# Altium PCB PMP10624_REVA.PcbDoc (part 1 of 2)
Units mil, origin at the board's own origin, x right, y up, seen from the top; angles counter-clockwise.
Board outline 2850 x 2600 mil, 4 copper layers (Top Layer, Signal Layer 1, Signal Layer 2, Bottom Layer), stack 61.2 mil thick; 108 components, 51 nets, 253 pads, 67 vias.
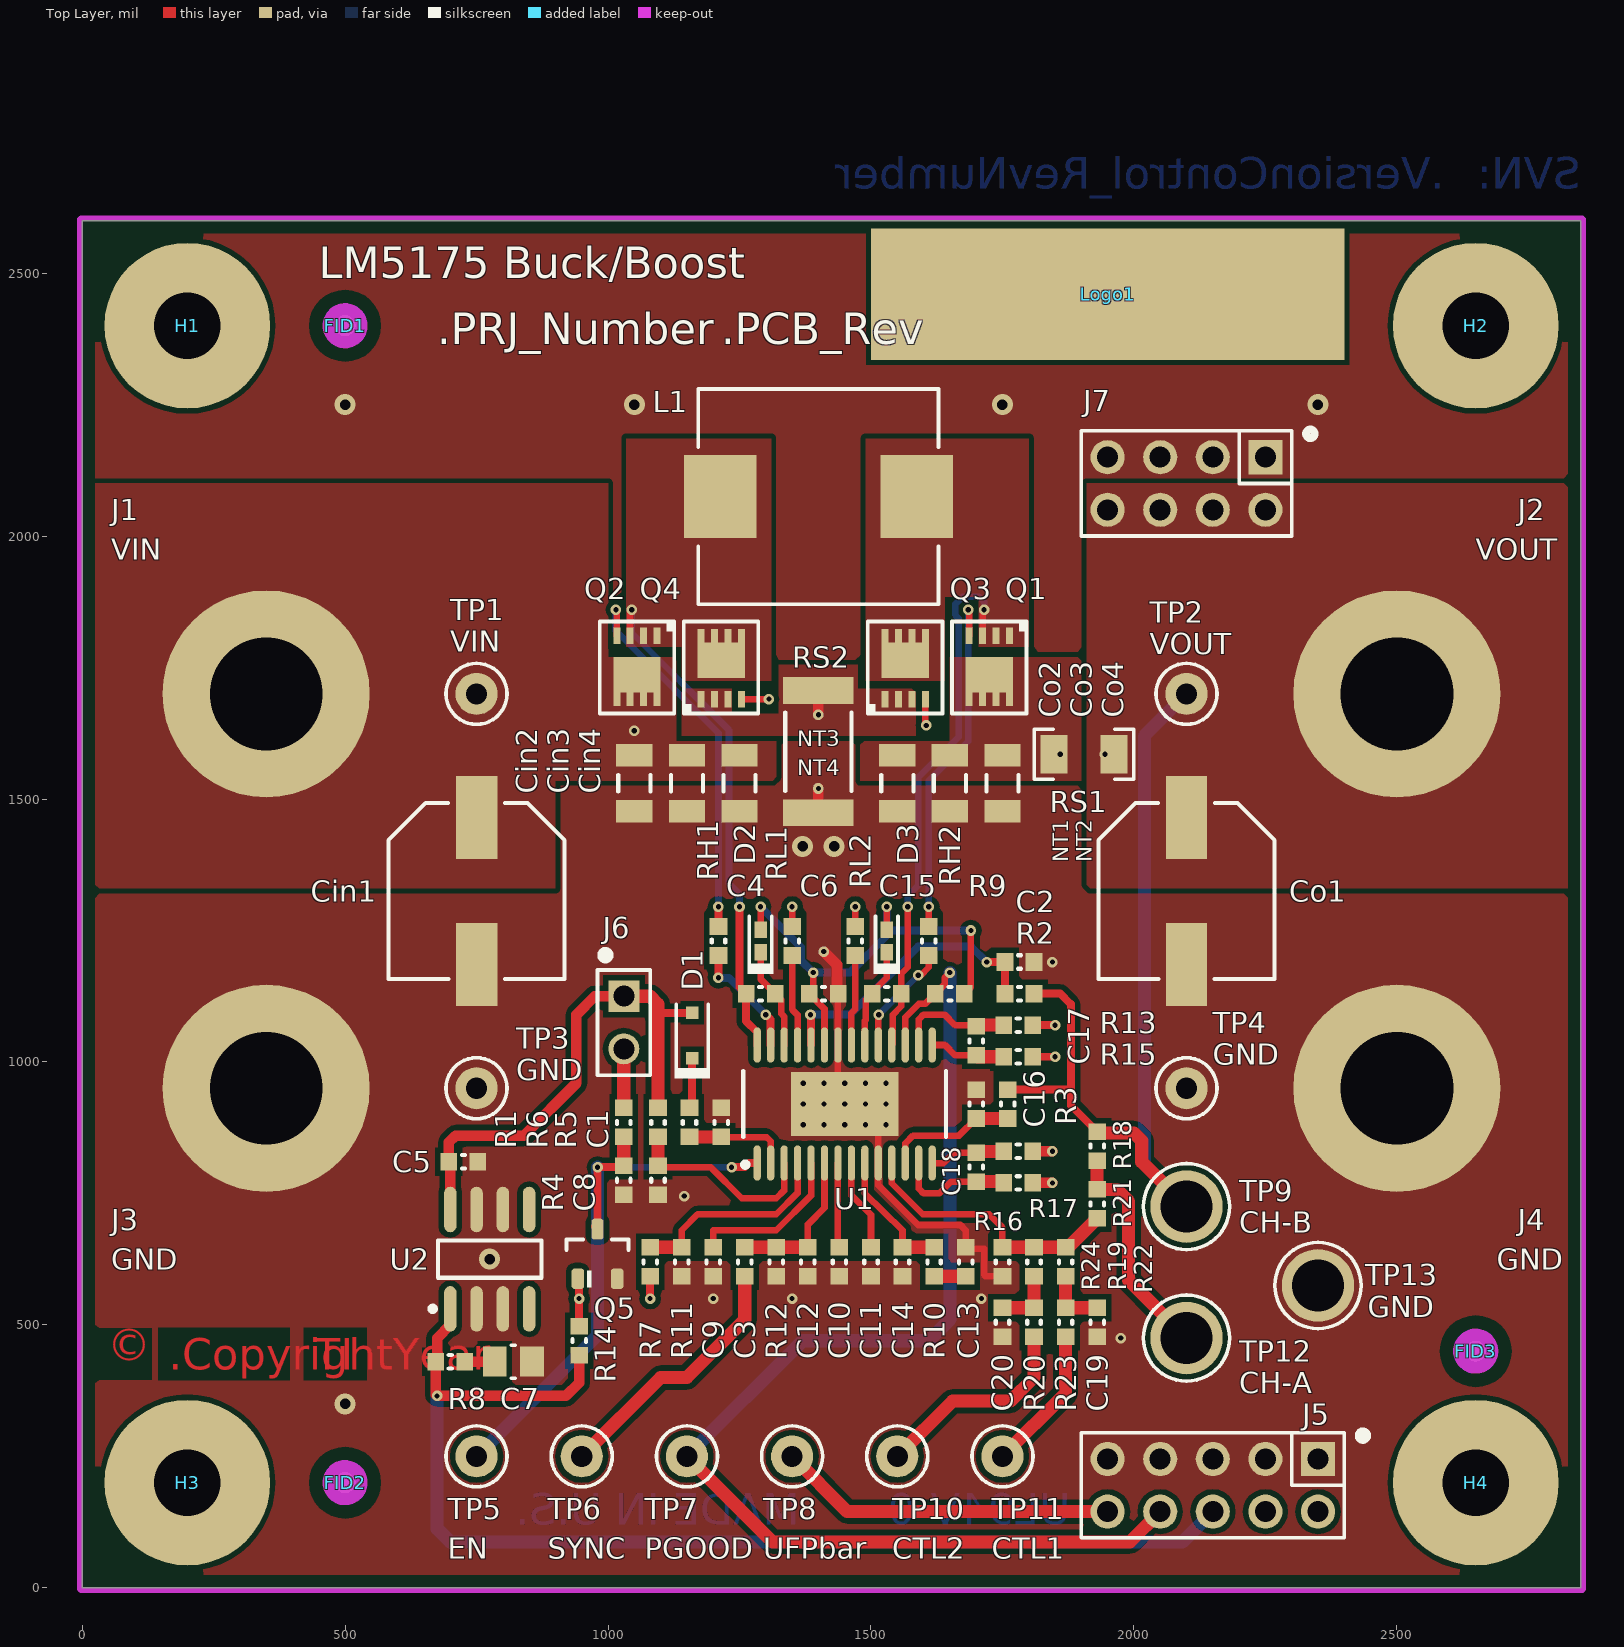
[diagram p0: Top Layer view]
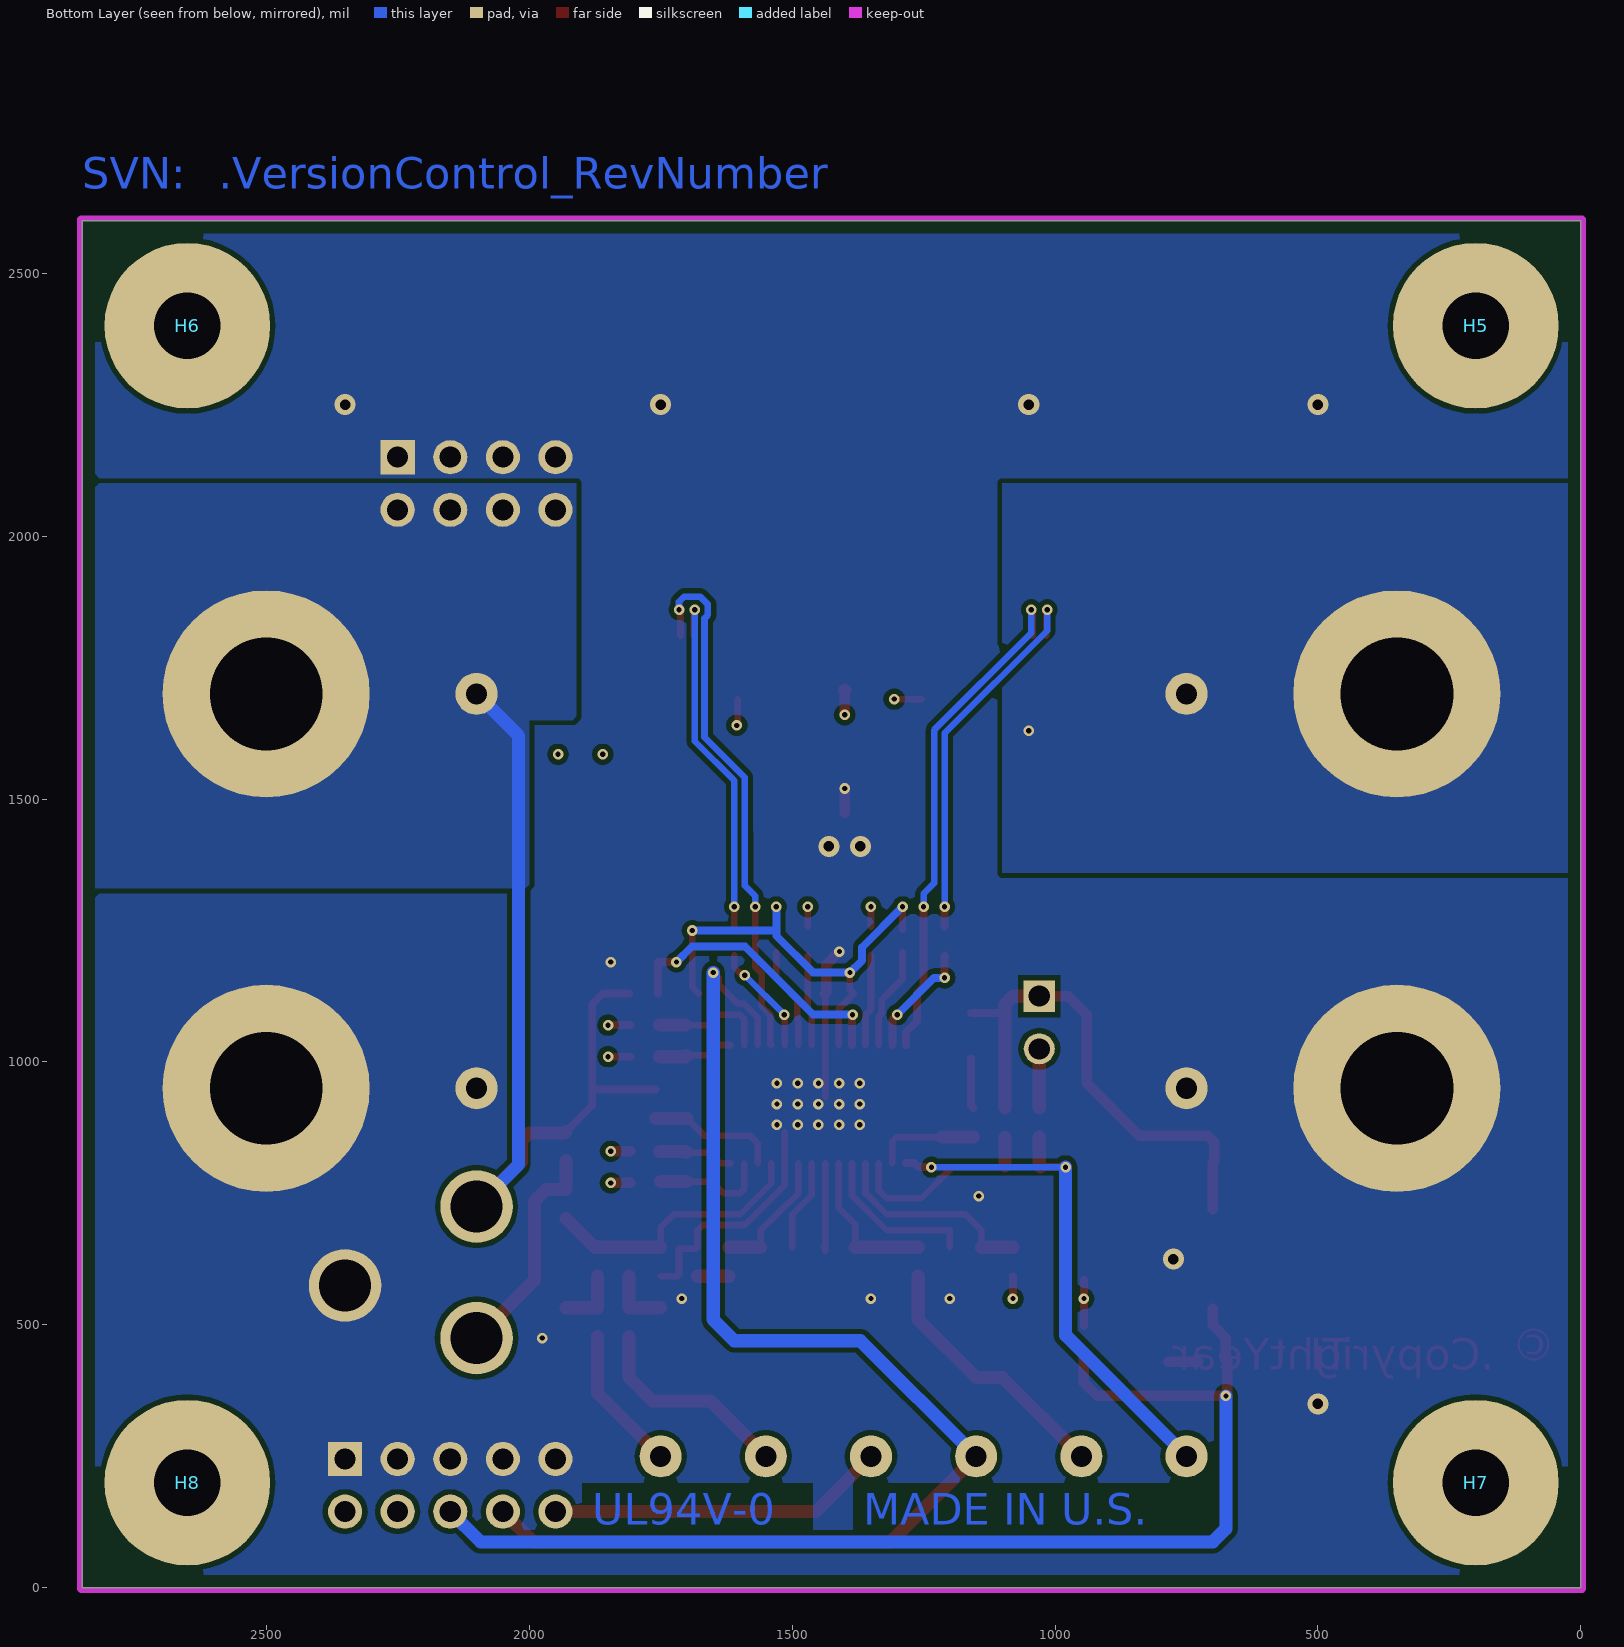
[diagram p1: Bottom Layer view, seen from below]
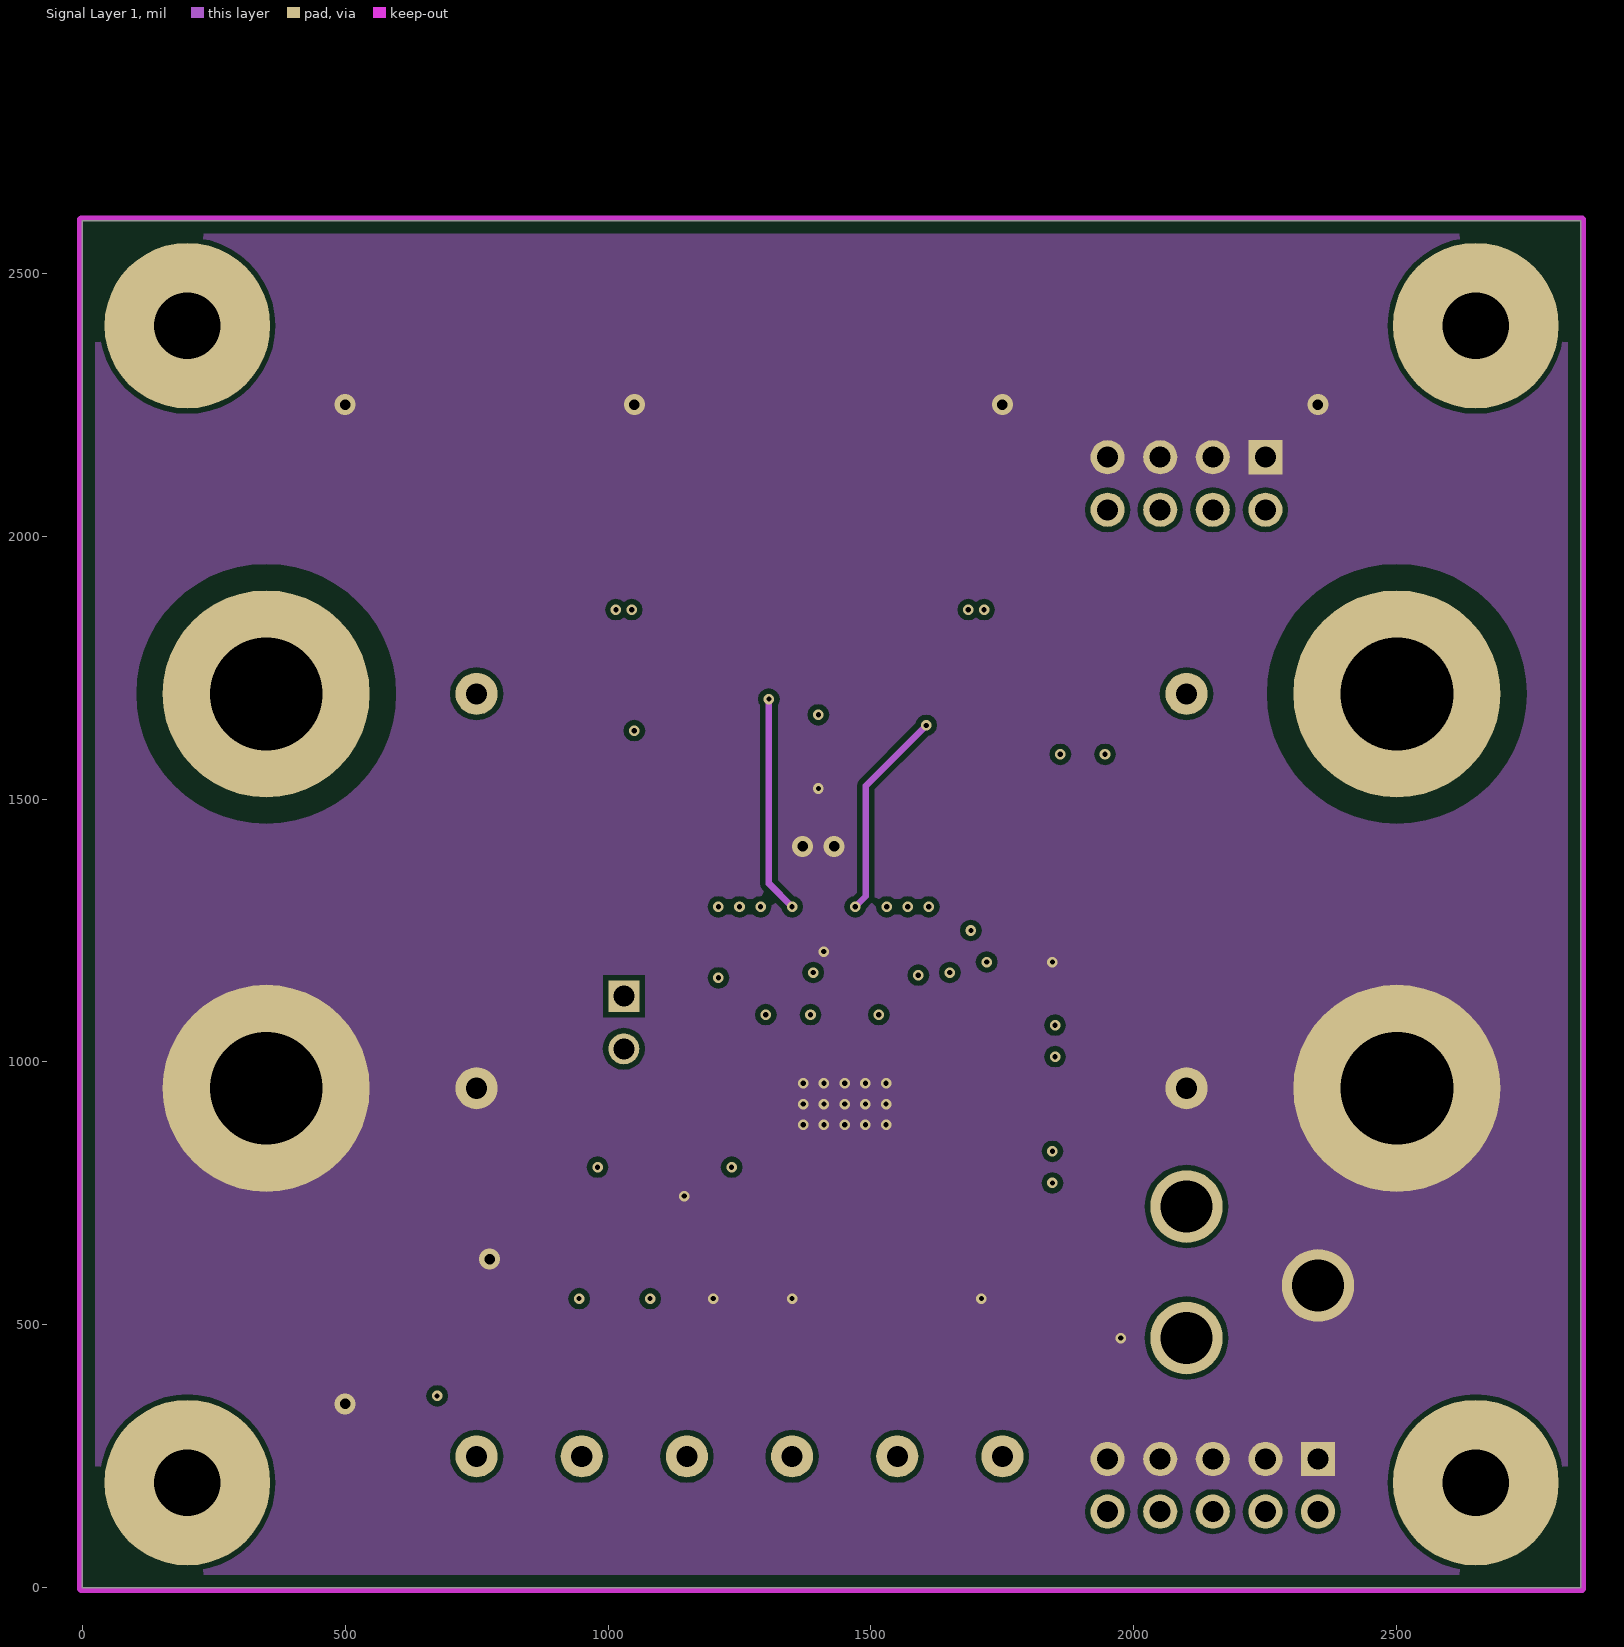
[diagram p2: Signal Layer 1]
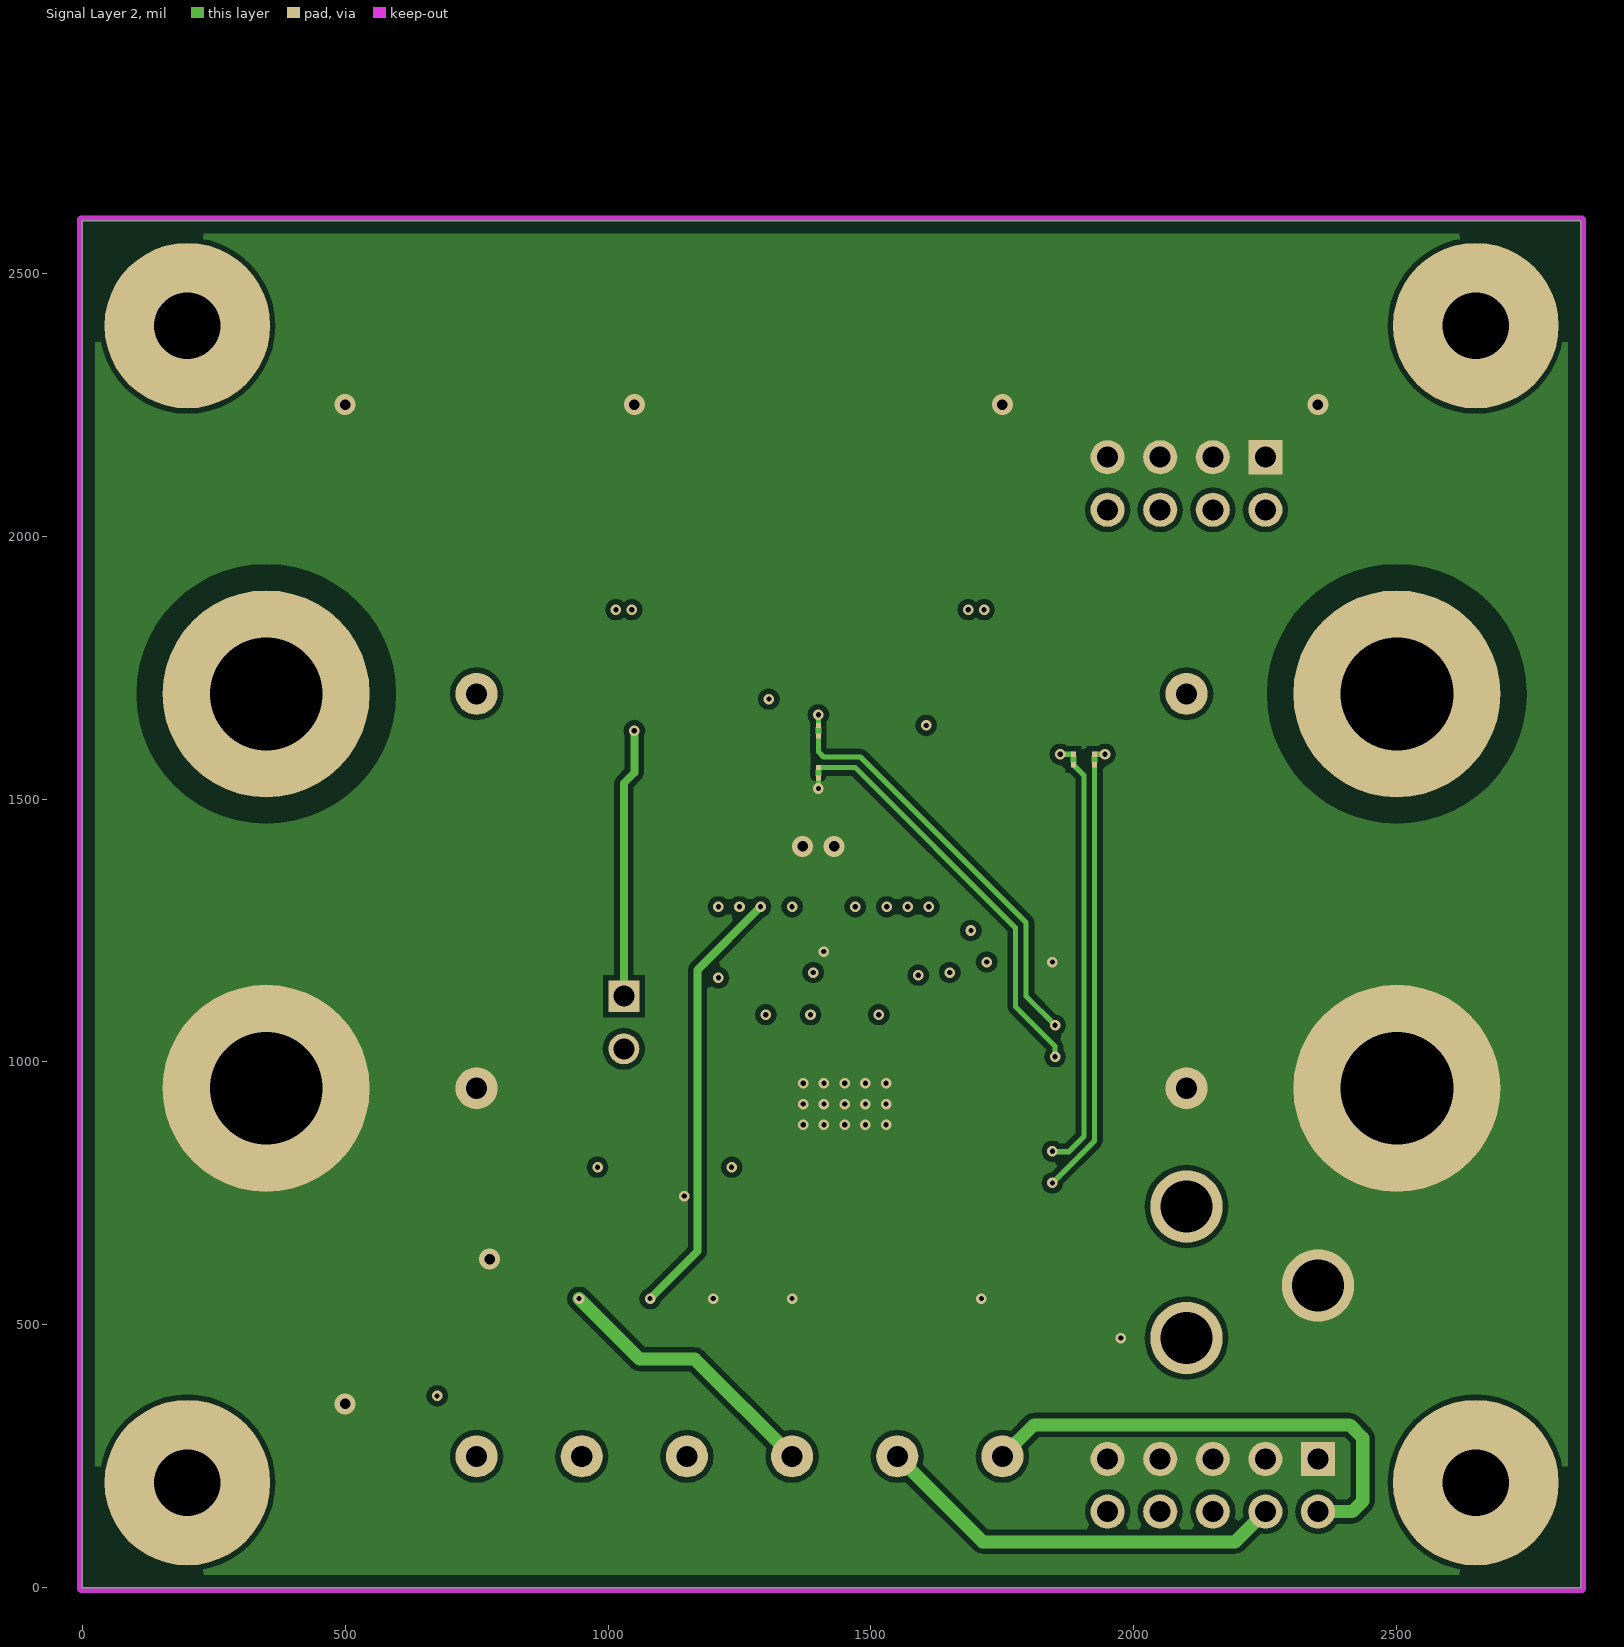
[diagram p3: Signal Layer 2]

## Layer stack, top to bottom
Top Solder: solder mask 0.4, Solder Resist, Dk 3.5
Top Layer: signal copper 2.8
Dielectric1: core 20, FR-4, Dk 4.8
Signal Layer 1: signal copper 1.4
Dielectric 2: prepreg 12.8, Dk 4.2
Signal Layer 2: signal copper 1.4
Dielectric 3: core 20, FR-4, Dk 4.8
Bottom Layer: signal copper 2.8
Bottom Solder: solder mask 0.4, Solder Resist, Dk 3.5

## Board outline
0,0 2850,0 2850,2600 0,2600

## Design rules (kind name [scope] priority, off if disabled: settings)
AcuteAngle [All] p1: minimum=4.50000000000000E+0001 checktracksonly=FALSE
AssemblyTestPointUsage [All] p1: valid=2
Clearance Clearance_IHLW [HasFootprint('IHLW-4040CF') vs IsKeepOut] p1: gap=10
Clearance Clearance_Keepouts [((IsTrack Or IsArc) And Not InPoly) And IsFree and IsKeepOut vs ((IsTrack Or IsArc) And Not InPoly) And IsFree and IsKeepOut] p2: gap=0
Clearance Clearance_BoardEdge_MountingHoles [OnCopper and InComponentClass('Mounting Holes') vs IsKeepOut] p3: gap=40
Clearance Clearance_BoardEdge_Poly [OnCopper and InPoly vs IsKeepOut] p4: gap=25
Clearance Clearance_BoardEdge [OnCopper and Not InComponentClass('Logo') and not InComponentClass('FiducialMark') and not InRegion(1000,500,4000,800) and Not IsKeepout vs IsKeepOut] p5: gap=75
Clearance Clearance_Poly [InPolygon] p6: gap=10
Clearance [All] p7: gap=5.91
ComponentClearance ComponentClearance_Shunt [InComponentClass('Header') vs InComponentClass('Shunt')] p1: gap=0 collisioncheckmode=3 verticalgap=0 showdistances=FALSE
ComponentClearance ComponentClearance_MountingHoles_FiducialMarks [InComponentClass('Mounting Holes') vs InComponentClass('FiducialMark')] p2: gap=50 collisioncheckmode=3 verticalgap=10 showdistances=FALSE
ComponentClearance ComponentClearance_Logo [InComponentClass('Logo')] p3: gap=50 collisioncheckmode=3 verticalgap=10 showdistances=FALSE
ComponentClearance ComponentClearance_ScrewToNut [(HasFootprint('NY PMS 440 0025 PH')) vs (HasFootprint('Keystone_1902C'))] p4: gap=5 collisioncheckmode=3 verticalgap=10 showdistances=FALSE
ComponentClearance ComponentClearance_MountingHoles [InComponentClass('Mounting Holes')] p5: gap=120 collisioncheckmode=3 verticalgap=100000 showdistances=FALSE
ComponentClearance ComponentClearance_SMTtoSMT [IsSMTComponent vs IsSMTComponent] p6: gap=20 collisioncheckmode=3 verticalgap=20 showdistances=FALSE
ComponentClearance ComponentClearance_SmallPassives [HasFootprint('0201*') or HasFootprint('0402*') or HasFootprint('0508') or HasFootprint('0603*') or HasFootprint('0612') or HasFootprint('0805*') or HasFootprint('0815*') or HasFootprint('0830*') or HasFootprint('1206*') or HasFootprint('1210*') or HasFootprint('1808*') or HasFootprint('1812*') or HasFootprint('1825*') or HasFootprint('2010*') or HasFootprint('2220*') or HasFootprint('2225*') or HasFootprint('2512*') or HasFootprint('2728*') or HasFootprint('3518*') or HasFootprint('Net-Tie_10mil') vs HasFootprint('0201*') or HasFootprint('0402*') or HasFootprint('0508') or HasFootprint('0603*') or HasFootprint('0612') or HasFootprint('0805*') or HasFootprint('0815*') or HasFootprint('0830*') or HasFootprint('1206*') or HasFootprint('1210*') or HasFootprint('1808*') or HasFootprint('1812*') or HasFootprint('1825*') or HasFootprint('2010*') or HasFootprint('2220*') or HasFootprint('2225*') or HasFootprint('2512*') or HasFootprint('2728*') or HasFootprint('3518*') or HasFootprint('Net-Tie_10mil')] p7: gap=20 collisioncheckmode=3 verticalgap=10 showdistances=FALSE
ComponentClearance ComponentClearance_THtoSMT [IsThruComponent vs IsSMTComponent] p8: gap=50 collisioncheckmode=3 verticalgap=30 showdistances=FALSE
ComponentClearance ComponentClearance_THtoTH [IsThruComponent vs IsThruComponent] p9: gap=100 collisioncheckmode=3 verticalgap=30 showdistances=FALSE
ComponentClearance [All] p10: gap=40 collisioncheckmode=3 verticalgap=10 showdistances=FALSE
DiffPairsRouting [All] p1: maxlimit=100 minlimit=10 mostfreqgap=10 toplayer_minwidth=7.5 toplayer_maxwidth=20 toplayer_prefwidth=15 midlayer1_minwidth=7.5 midlayer1_maxwidth=20 midlayer1_prefwidth=15 midlayer2_minwidth=7.5 midlayer2_maxwidth=20 midlayer2_prefwidth=15 bottomlayer_minwidth=7.5 bottomlayer_maxwidth=20 bottomlayer_prefwidth=15 maxuncoupledlength=1000
FabricationTestPointUsage TestPointUsage [All] p1: valid=2 allowmultiple=FALSE
FabricationTestpoint Testpoint [All] p1: side=3 testpointundercomponent=TRUE minsize=40 maxsize=100 preferedsize=60 minholesize=0 maxholesize=40 preferedholesize=32 testpointgrid=1 allowsidetop=TRUE allowsidebottom=TRUE usegrid=TRUE gridtolerance=0.01
FanoutControl Fanout_LCC [IsLCC] p1: bgadir=Out bgaviamode=Centered fanoutstyle=Auto fanoutdirection=Alternating viagrid=1 // Fanout_LCC (Default Rule)
FanoutControl Fanout_BGA [IsBGA] p2: bgadir=Out bgaviamode=Centered fanoutstyle=Auto fanoutdirection=Alternating viagrid=1 // Fanout_BGA (Default Rule)
FanoutControl Fanout_Default [All] p4: bgadir=Out bgaviamode=Centered fanoutstyle=Auto fanoutdirection=Alternating viagrid=1 // Fanout_Default (Default Rule)
FanoutControl Fanout_Small [(CompPinCount < 5)] p5: bgadir=Out bgaviamode=Centered fanoutstyle=Auto fanoutdirection=OutThenIn viagrid=1 // Fanout_Small (Default Rule)
HoleSize [All] p1: absolutevalues=TRUE maxlimit=271 minlimit=8 maxpercent=80.000 minpercent=20.000
MinimumAnnularRing MinimumAnnularRing_ThermalPadVias [IsVia and InAnyComponent] p1: minimumring=5
MinimumAnnularRing [All] p2: minimumring=5
MinimumSolderMaskSliver MinimumSolderMaskSliver_Logo [InComponentClass('Logo') vs InComponentClass('Logo')] p1: minsoldermaskwidth=0.7
MinimumSolderMaskSliver [All] p2: minsoldermaskwidth=2.95
PlaneConnect [All] p1: planeconnectstyle=Direct reliefexpansion=10 reliefentries=4 reliefconductorwidth=10 reliefairgap=10
PolygonConnect [All] p1: connectstyle=Direct reliefconductorwidth=10 reliefentries=4 polygonreliefangle="90 Angle" airgapwidth=10
RoutingVias ThermalPadVias [IsVia and InAnyComponent] p1: holewidth=7.87 width=19.68 viastyle="Through Hole" minholewidth=7.87 minwidth=19.68 maxholewidth=12.99 maxwidth=23.62
RoutingVias [All] p2: holewidth=16 width=34 viastyle="Through Hole" minholewidth=7.87 minwidth=20 maxholewidth=40 maxwidth=65
SilkToBoardRegionClearance [Not ((IsComment or IsDesignator) And (Hide <> 'False')) and not InRegion(1000,500,4000,800)] p1:
SilkToSilkClearance SilkToSilkClearance_Pb-FreeLogo [(HasFootprint('Pb-Free_Overlay_Medium') OR HasFootprint('Pb-Free_Overlay_Small')) vs (HasFootprint('Pb-Free_Overlay_Medium') OR HasFootprint('Pb-Free_Overlay_Small'))] p1: silktosilkclearance=0
SilkToSilkClearance [All] p2: silktosilkclearance=5
SilkToSolderMaskClearance "Silk to Solder Mask Opening" [All] p1: minsilkscreentomaskgap=1 clearancetoexposedcopper=FALSE
SolderMaskExpansion [All] p1: expansion=1.97
UnpouredPolygon [All] p1: allowunpoured=FALSE
Width [All] p1: maxlimit=100 minlimit=6 preferedwidth=10 checkconnectedcopper=TRUE
14 further rules are at their usual default settings.

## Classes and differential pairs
component class "Mounting Holes": H1 H2 H3 H4
component class Logo: Logo1
component class PMP10624_REVA_Sh2: FID1 FID2 FID3 H1 H2 H3 H4 H5 H6 H7 H8 Logo1 ZZ1 ZZ2 ZZ3
component class FiducialMark: FID1 FID2 FID3
component class AssemblyNote: ZZ1 ZZ2 ZZ3
component class Header: J5 J6 J7
differential pair ISNS_OUT: +ISNS_OUT_P -ISNS_OUT_N
differential pair HDRV2: +HDRV2_P -HDRV2_N
differential pair HDRV1: +HDRV1_P -HDRV1_N
differential pair CS: +CS_P -CS_N

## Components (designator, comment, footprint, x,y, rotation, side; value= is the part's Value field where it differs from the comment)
C1 "C1608X7R1H224K080AB" 0603L 1215,885 r90 top
C2 "C1608X7R1H224K080AB" 0603L 1782.44,1190 r0 top
C3 "GRM1885C1H101JA01D" 0603L 1260,620 r90 top
C4 "06033C104JAT2A" 0603L 1290,1130 r180 top
C5 "C1608X7R1H224K080AB" 0603L 725,810 r0 top
C6 "GRM188R71C105KA12D" 0603L 1410,1130 r0 top
C7 "EMK212BB7106MG-T" 0805_145 820,430 r0 top
C8 "C1608X7R1H224K080AB" 0603L 1095,775 r90 top
C9 "CRCW06030000Z0EA" 0603L 1200,620 r90 top
C10 "GRM1885C1H101JA01D" 0603L 1440,620 r270 top
C11 "GRM188R71H473KA61D" 0603L 1500,620 r270 top
C12 "DNP" 0603L 1380,620 r90 top
C13 "GRM188R71H223KA01D" 0603L 1680,620 r90 top
C14 "GRM1885C1H101JA01D" 0603L 1560,620 r270 top
C15 "06033C104JAT2A" 0603L 1530,1130 r180 top
C16 "C1608X7R1H224K080AB" 0603L 1700,920 r90 top
C17 "DNP" 0603L 1700,1040 r270 top
C18 "DNP" 0603L 1700,800 r90 top
C19 "06033C104JAT2A" 0603L 1930,505 r270 top
C20 "06033C104JAT2A" 0603L 1750,505 r270 top
Cin1 "EEE-FK1J680UP" SM_RADIAL_F 750,1325 r270 top
Cin2 "GRM31CR71H475KA12L" 1206L 1050,1530 r270 top
Cin3 "GRM31CR71H475KA12L" 1206L 1150,1530 r270 top
Cin4 "GRM31CR71H475KA12L" 1206L 1250,1530 r270 top
Co1 "EEE-FK1J680UP" SM_RADIAL_F 2100,1325 r270 top
Co2 "GRM31CR71H475KA12L" 1206L 1550,1530 r270 top
Co3 "GRM31CR71H475KA12L" 1206L 1650,1530 r270 top
Co4 "GRM31CR71H475KA12L" 1206L 1750,1530 r270 top
D1 "BAT54HT1G" sod-323 1160,1050 r90 top
D2 "BAS516,115" SOD-523 1290,1230 r90 top
D3 "BAS516,115" SOD-523 1530,1230 r90 top
FID1 "Fiducial" Fiducial10-20 500,2400 r0 top
FID2 "Fiducial" Fiducial10-20 500,200 r0 top
FID3 "Fiducial" Fiducial10-20 2650,450 r0 top
H1 "NY PMS 440 0025 PH" "NY PMS 440 0025 PH" 200,2400 r0 top locked
H2 "NY PMS 440 0025 PH" "NY PMS 440 0025 PH" 2650,2400 r0 top locked
H3 "NY PMS 440 0025 PH" "NY PMS 440 0025 PH" 200,200 r0 top locked
H4 "NY PMS 440 0025 PH" "NY PMS 440 0025 PH" 2650,200 r0 top locked
H5 "1902C" Keystone_1902C 200,2400 r180 bottom locked
H6 "1902C" Keystone_1902C 2650,2400 r180 bottom locked
H7 "1902C" Keystone_1902C 200,200 r180 bottom locked
H8 "1902C" Keystone_1902C 2650,200 r180 bottom locked
J1 "VIN" Keystone_575-4 350,1700 r0 top
J2 "VOUT" Keystone_575-4 2500,1700 r0 top
J3 "GND" Keystone_575-4 350,950 r0 top
J4 "GND" Keystone_575-4 2500,950 r0 top
J5 "PEC05DAAN" CONN_PEC05DAAN 2150,195 r180 top
J6 "PEC02SAAN" CONN_PEC02SAAN 1030,1075 r270 top
J7 "PEC04DAAN" CONN_PEC04DAAN 2100,2100 r180 top
L1 "IHLP4040DZER6R8M01" IHLP-4040DZ 1400,2075 r0 top
Logo1 "Texas Instruments" TI_Stacked_SolderMask_Small 1950,2460 r0 top
NT1 "Net-Tie" Net-Tie_10mil 1885,1575 r90 top net-tie
NT2 "Net-Tie" Net-Tie_10mil 1925,1575 r90 top net-tie
NT3 "Net-Tie" Net-Tie_10mil 1400,1630 r270 top net-tie
NT4 "Net-Tie" Net-Tie_10mil 1400,1550 r90 top net-tie
Q1 "BSZ0902NS" PG-TSDSON-8 1725,1750 r270 top
Q2 "BSZ042N06NS" PG-TSDSON-8 1055,1750 r270 top
Q3 "BSZ0902NS" PG-TSDSON-8 1565,1750 r90 top
Q4 "BSZ042N06NS" PG-TSDSON-8 1215,1750 r90 top
Q5 "2N7002-7-F" SOT-23 980,635 r90 top
R1 "CRCW0603130KJNEA" 0603L 1030,885 r90 top
R2 "CRCW060310R0JNEA" 0603L 1782.44,1130 r0 top
R3 "CRCW060310R0JNEA" 0603L 1760,920 r90 top
R4 "CRCW060323K7FKEA" 0603L 1030,775 r90 top
R5 "CRCW060310R0JNEA" 0603L 1155,885 r90 top
R6 "CRCW060310R0JNEA" 0603L 1095,885 r270 top
R7 "DNP" 0603L 1080,620 r270 top
R8 "CRCW06031R00JNEA" 0603L 700,430 r180 top
R9 "CRCW060320K0JNEA" 0603L 1650,1130 r0 top
R10 "CRCW060347K0JNEA" 0603L 1620,620 r90 top
R11 "CRCW060349K9FKEA" 0603L 1140,620 r90 top
R12 "CRCW060364K9FKEA" 0603L 1320,620 r90 top
R13 "CRCW06030000Z0EA" 0603L 1780,1070 r0 top
R14 "CRCW0603100KJNEA" 0603L 945,470 r270 top
R15 "CRCW06030000Z0EA" 0603L 1780,1010 r0 top
R16 "CRCW06030000Z0EA" 0603L 1780,770 r180 top
R17 "CRCW06030000Z0EA" 0603L 1780,830 r180 top
R18 "CRCW060347R0JNEA" 0603L 1930,840 r270 top
R19 "CRCW06034K99FKEA" 0603L 1810,620 r90 top
R20 "CRCW06034K99FKEA" 0603L 1810,505 r90 top
R21 "CRCW060349K9FKEA" 0603L 1930,730 r90 top
R22 "CRCW06036K65FKEA" 0603L 1870,620 r90 top
R23 "CRCW06036K65FKEA" 0603L 1870,505 r90 top
R24 "CRCW06039K53FKEA" 0603L 1750,620 r90 top
RH1 "CRCW06030000Z0EA" 0603L 1210,1230 r90 top
RH2 "CRCW06030000Z0EA" 0603L 1610,1230 r270 top
RL1 "CRCW06030000Z0EA" 0603L 1350,1230 r90 top
RL2 "CRCW06030000Z0EA" 0603L 1470,1230 r270 top
RS1 "CSR1206FK12L0" 1206 1905,1585 r0 top
RS2 "CSRN2512FK15L0" 2512 1400,1590 r90 top
TP1 "VIN" Keystone5000 750,1700 r0 top
TP2 "VOUT" Keystone5000 2100,1700 r0 top
TP3 "GND" Keystone5001 750,950 r0 top
TP4 "GND" Keystone5001 2100,950 r0 top
TP5 "EN" Keystone5002 750,250 r0 top
TP6 "SYNC" Keystone5002 950,250 r0 top
TP7 "PGOOD" Keystone5002 1150,250 r0 top
TP8 "UFPbar" Keystone5002 1350,250 r0 top
TP9 "CH-B" Keystone1598-2 2100,725 r0 top
TP10 "CTL2" Keystone5002 1550,250 r0 top
TP11 "CTL1" Keystone5002 1750,250 r0 top
TP12 "CH-A" Keystone1598-2 2100,475 r0 top
TP13 "GND" Keystone1598-2 2350,575 r0 top
U1 "LM5175PWP" PWP0028F_N 1450,920 r90 top
U2 "LM2936MX-3.3" M08A_N 775,625 r90 top
ZZ1 "These assemblies are ESD sensitive, ESD precautions shall be observed." AssemblyNote 185,3829.11 r0 top
ZZ2 "These assemblies must be clean and free from flux and all contaminants. Use of no clean flux is not acceptable." AssemblyNote 185,3740.56 r0 top
ZZ3 "These assemblies must comply with workmanship standards IPC-A-610 Class 2, unless otherwise specified." AssemblyNote 185,3652 r0 top

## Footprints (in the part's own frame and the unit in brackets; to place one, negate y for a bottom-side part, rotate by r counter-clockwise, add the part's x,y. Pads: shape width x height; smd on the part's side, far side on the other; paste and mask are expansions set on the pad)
0603L [mm] "0603 from SM-752 data"
  rect 0.8x0.85 smd: 1(-0.7,0) 2(0.7,0)
  silkscreen extent -0.07,-0.33 0.07,0.33, body extent -0.87,-0.47 0.87,0.47, height 0.85
0805_145 [mm] "0805 / 1.45mm height"
  rect 1.15x1.45 smd: 1(-0.9,0) 2(0.9,0)
  silkscreen extent -0.1,-0.8 0.1,0.8, body extent -1.1,-0.72 1.1,0.72, height 1.45
1206 [mm] "1206 from SM-752 data"
  rect 1.3x1.85 smd: 1(-1.45,0) 2(1.45,0)
  silkscreen extent -2.4,-1.21 2.4,1.21, body extent -1.7,-0.9 1.7,0.9, height 1.35
1206L [mm] "1206 from SM-752 data"
  rect 1.1x1.75 smd: 1(-1.35,0) 2(1.35,0)
  silkscreen extent -0.4,-0.77 0.4,0.77, body extent -1.7,-0.9 1.7,0.9, height 1.35
2512 [mm] "Chip Resistor, Body 6.3x3.2mm, IPC Medium Density"
  rect 1.3x3.4 smd: 1(-2.95,0) 2(2.95,0)
  silkscreen extent -1.9,-1.6 1.9,1.6, body extent -3.22,-1.67 3.22,1.67, height 0.71
AssemblyNote [mil] "Assembly Note"
CONN_PEC02SAAN [mm] "SULLINS"
  rect 1.5x1.5 hole 1.016: 1(-1.27,0)
  round 1.5 hole 1.016: 2(1.27,0)
  silkscreen extent -3.45,-1.27 2.54,1.27, body extent -2.54,-1.27 2.54,1.27, height 8.38
CONN_PEC04DAAN [mm] "SULLINS"
  rect 1.65x1.65 hole 1.016 mask+0: 1(-3.81,-1.27)
  round 1.65 hole 1.016 mask+0: 2(-3.81,1.27) 3(-1.27,-1.27) 4(-1.27,1.27) 5(1.27,-1.27) 6(1.27,1.27) 7(3.81,-1.27) 8(3.81,1.27)
  silkscreen extent -6.18,-2.6 5.08,2.54, body extent -5.08,-2.54 5.08,2.54, height 8.38
CONN_PEC05DAAN [mm] "SULLINS"
  rect 1.65x1.65 hole 1.016 mask+0: 1(-5.08,-1.27)
  round 1.65 hole 1.016 mask+0: 2(-5.08,1.27) 3(-2.54,-1.27) 4(-2.54,1.27) 5(0,-1.27) 6(0,1.27) 7(2.54,-1.27) 8(2.54,1.27) 9(5.08,-1.27) 10(5.08,1.27)
  silkscreen extent -7.45,-2.6 6.35,2.54, body extent -6.35,-2.54 6.35,2.54, height 8.38
Fiducial10-20 [mm]
  round 1 smd mask+0.5: 1(0,0)
  Top Layer keep-out circle w1.178: c0,0 r0.5
IHLP-4040DZ [mm] "Vishay Dale recommended land pattern.  Document 34192 rev 04-Jul-08"
  rect 3.5x4 smd: 1(-4.75,0) 2(4.75,0)
  silkscreen extent -5.8,-5.2 5.8,5.2, body extent -5.75,-5.15 5.75,5.15, height 4
Keystone1598-2 [mm] "Triple Turret"
  round 3.5 hole 2.5: 1(0,0)
  silkscreen extent -2.08,-2.08 2.08,2.08, body extent -1.6,-1.6 1.59,1.6, height 7.72
Keystone5000 [mil] "For Keystone 500x miniature loop terminals"
  round 80 hole 40: 1(0,0)
  silkscreen extent -58,-58 58,58, body extent -49,-49 49,49, height 182
Keystone5001 [mil] "For Keystone 500x miniature loop terminals"
  round 80 hole 40: 1(0,0)
  silkscreen extent -58,-58 58,58, body extent -49,-49 49,49, height 182
Keystone5002 [mil] "For Keystone 500x miniature loop terminals"
  round 80 hole 40: 1(0,0)
  silkscreen extent -58,-58 58,58, body extent -49,-49 49,49, height 182
Keystone_575-4 [mm] "Banana Jack"
  round 10 hole 5.45: 1(0,0)
  body extent -3.95,-3.95 3.92,3.93, height 2.36
Keystone_1902C [mil] "Hex Standoff, 4-40 threaded, nylon"
  body extent -145,-126 146,126, height 501
M08A_N [mm] "SOIC, 8-Leads, Body 4.9x3.9mm, Pitch 1.27mm, IPC Medium Density"
  oval 2.2x0.6 smd: 1(-2.4,1.905) 2(-2.4,0.635) 3(-2.4,-0.635) 4(-2.4,-1.905) 5(2.4,-1.905) 6(2.4,-0.635) 7(2.4,0.635) 8(2.4,1.905)
  silkscreen extent -2.52,-2.5 0.9,2.88, body extent -2,-2.5 2,2.5, height 1.75
Net-Tie_10mil [mil] "10mil net tie, no solder mask opening, no solder paste"
  rect 10x10 on Mid2 paste-5 mask-5: 1(-10,0) 2(10,0)
  Signal Layer 2 region: -6,5 6,5 6,-5 -6,-5
"NY PMS 440 0025 PH" [mm] "4-40 nylon screw and mounting hole"
  round 8 hole 3.2: 1(0,0)
  body extent -3.3,-3.3 3.3,3.3, height 2.69
PG-TSDSON-8 [mm] "Infineon recommended land pattern"
  rect 0.8x0.34 smd: 1(-1.538,0.975) 2(-1.538,0.325) 3(-1.538,-0.325) 4(-1.538,-0.975)
  rect 0.65x0.34 smd: 5(1.538,-0.975) 6(1.538,-0.325) 7(1.538,0.325) 8(1.538,0.975)
  rect 1.71x2.29 smd: 9(0.358,0)
  silkscreen extent -2.22,-1.8 2.22,1.8, body extent -1.7,-1.7 1.7,1.7, height 1.1
PWP0028F_N [mm] "TSOP, 28-Leads, Body 9.7x4.4mm, Pitch 0.65mm, Exposed Pad, IPC Medium Density"
  oval 1.7x0.35 smd: 1(-2.85,4.225) 2(-2.85,3.575) 3(-2.85,2.925) 4(-2.85,2.275) 5(-2.85,1.625) 6(-2.85,0.975) 7(-2.85,0.325) 8(-2.85,-0.325) 9(-2.85,-0.975) 10(-2.85,-1.625) 11(-2.85,-2.275) 12(-2.85,-2.925) 13(-2.85,-3.575) 14(-2.85,-4.225) 15(2.85,-4.225) 16(2.85,-3.575) 17(2.85,-2.925) 18(2.85,-2.275) 19(2.85,-1.625) 20(2.85,-0.975) 21(2.85,-0.325) 22(2.85,0.325) 23(2.85,0.975) 24(2.85,1.625) 25(2.85,2.275) 26(2.85,2.925) 27(2.85,3.575) 28(2.85,4.225)
  rect 3.1x5.18 smd: 29(0,0)
  silkscreen extent -3.05,-4.9 1.6,4.92, body extent -3.21,-4.85 3.21,4.85, height 0.98
SM_RADIAL_F [mm] "8 x 10.2mm:  Panasonic F"
  rect 4x2 smd: 1(-3.55,0) 2(3.55,0)
  silkscreen extent -4.25,-4.25 4.25,4.25, body extent -4.26,-4.26 4.26,4.26, height 10.5
sod-323 [mm] "NXP recommended land pattern"
  rect 0.6x0.6 smd paste-0.05: 1(-1.1,0) 2(1.1,0)
  silkscreen extent -2.06,-0.86 1.53,0.86, body extent -1.3,-0.67 1.3,0.68, height 1.1
SOD-523 [mm] "NXP Semiconductor recommended land pattern, nominal STEP model"
  rect 0.8x0.6 smd paste-0.05: 1(-0.55,0) 2(0.55,0)
  silkscreen extent -1.6,-0.64 1.2,0.63, body extent -0.8,-0.4 0.8,0.4, height 0.72
SOT-23 [mm] "SOT23, 3-Leads, Body 2.9x1.3mm, Pitch 0.95mm, Lead Span 2.5mm, IPC Medium Density"
  rrect50% 1x0.6 smd: 1(-1.2,0.95) 2(-1.2,-0.95) 3(1.2,0)
  silkscreen extent -1.63,-1.5 0.7,1.5, body extent -1.16,-1.45 1.21,1.45, height 1
TI_Stacked_SolderMask_Small [mil]
  rect 900x250 smd paste-125 mask-125: 0(0,0)

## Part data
C1 C2 C5: "CAP, CERM, 0.22uF, 50V, +/-10%, X7R, 0603"
C3 C10 C14: "CAP, CERM, 100 pF, 50 V, +/- 5%, C0G/NP0, 0603"
C4 C15 C19 C20: "CAP, CERM, 0.1 µF, 25 V, +/- 5%, X7R, 0603"
C6: "CAP, CERM, 1uF, 16V, +/-10%, X7R, 0603"
C7: "CAP, CERM, 10 µF, 16 V, +/- 20%, X7R, 0805"
C8 C16: "CAP, CERM, 0.22 µF, 50 V, +/- 10%, X7R, 0603"
C9: "RES, 0, 5%, 0.1 W, 0603"
C11: "CAP, CERM, 0.047 µF, 50 V, +/- 10%, X7R, 0603"
C12 C17 C18: library part GRM1885C1H101JA01D, "CAP, CERM, 100pF, 50V, +/-5%, C0G/NP0, 0603"
C13: "CAP, CERM, 0.022 µF, 50 V, +/- 10%, X7R, 0603"
Cin1 Co1: "CAP, AL, 68 µF, 63 V, +/- 20%, 0.65 ohm, SMD"
Cin2 Cin3 Cin4 Co2 Co3 Co4: "CAP, CERM, 4.7 µF, 50 V, +/- 10%, X7R, 1206"
D1: "Diode, Schottky, 30V, 0.2A, SOD-323"
D2 D3: "Diode, Switching, 100V, 0.25A, SOD-523"
FID1 FID2 FID3: "Fiducial mark.  There is nothing to buy or mount."
H1 H2 H3 H4: "Machine Screw, Round, #4-40 x 1/4, Nylon, Philips panhead"
H5 H6 H7 H8: "Standoff, Hex, 0.5\"L #4-40 Nylon"
J1 J2 J3 J4: library part 575-4, "Standard Banana Jack, Uninsulated, 5.5mm"
J5: "Header, 100mil, 5x2, Tin, TH"
J6: "Header, 100mil, 2x1, Tin, TH"
J7: "Header, 100mil, 4x2, Tin, TH"
L1: "Inductor, Shielded, Powdered Iron, 6.8 µH, 8 A, 0.0233 ohm, SMD"
Logo1: library part TI_Logo, "Texas Instrument Corporate Signature"
NT1 NT2 NT3 NT4: "Single point connection between nets."
Q1 Q3: "MOSFET, N-CH, 30 V, 40 A, PG-TSDSON-8"
Q2 Q4: "MOSFET, N-CH, 60 V, 17 A, PG-TSDSON-8"
Q5: "MOSFET, N-CH, 60 V, 0.17 A, SOT-23"
R1: "RES, 130 k, 5%, 0.1 W, 0603"
R2 R3 R5 R6: "RES, 10, 5%, 0.1 W, 0603"
R4: "RES, 23.7 k, 1%, 0.1 W, 0603"
R7: library part CRCW06030000Z0EA, "RES, 0, 5%, 0.1 W, 0603"
R8: "RES, 1.0, 5%, 0.1 W, 0603"
R9: "RES, 20 k, 5%, 0.1 W, 0603"
R10: "RES, 47 k, 5%, 0.1 W, 0603"
R11 R21: "RES, 49.9 k, 1%, 0.1 W, 0603"
R12: "RES, 64.9 k, 1%, 0.1 W, 0603"
R13 R15 R16 R17 RH1 RH2 RL1 RL2: "RES, 0 ohm, 5%, 0.1W, 0603"
R14: "RES, 100 k, 5%, 0.1 W, 0603"
R18: "RES, 47, 5%, 0.1 W, 0603"
R19 R20: "RES, 4.99 k, 1%, 0.1 W, 0603"
R22 R23: "RES, 6.65 k, 1%, 0.1 W, 0603"
R24: "RES, 9.53 k, 1%, 0.1 W, 0603"
RS1: "RES, 0.012, 1%, 0.5 W, 1206"
RS2: "RES, 0.015, 1%, 2 W, 2512"
TP1 TP2: library part 5000, "Test Point, TH, Miniature, Red"
TP3 TP4: library part 5001, "Test Point, TH, Miniature, Black"
TP5 TP6 TP7 TP8 TP10 TP11: library part 5002, "Test Point, Miniature, White, TH"
TP9 TP12 TP13: library part 1598-2, "Terminal, Turret, TH, Triple"
U1: "42V Wide VIN 4-Switch Synchronous Buck-Boost Controller, PWP0028F"
U2: "Ultra-Low Quiescent Current LDO Voltage Regulator, 8-pin Narrow SOIC"
ZZ1 ZZ2 ZZ3: library part AssemblyNote

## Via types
v1: diameter 20, hole 10, Top Layer to Bottom Layer, 59 vias
v2: diameter 40, hole 20, Top Layer to Bottom Layer, 8 vias

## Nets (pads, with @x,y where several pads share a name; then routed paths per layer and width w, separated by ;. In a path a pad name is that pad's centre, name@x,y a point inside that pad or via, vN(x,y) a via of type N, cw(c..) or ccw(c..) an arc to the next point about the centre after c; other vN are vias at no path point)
BIAS: C2.1 R2.1 U1.24 | length 553.8
  Top Layer w15: v1(1385,1090) 1386.02,1088.98 U1.24@1386.02,1032.2 ; v1(1720,1190) C2.1@1754.88,1190 R2.1@1754.88,1130
  Bottom Layer w15: v1(1385,1090) 1460,1090 1589.33,1219.33 1690.67,1219.33 v1(1720,1190)
BOOT1: C4.1 D2.1 U1.26 | length 194.7
  Top Layer w12.5: D2.1@1290,1208.35 1290,1157.56 C4.1@1317.56,1130 1329.63,1117.93 1329.63,1091.56 1334.84,1086.34 U1.26@1334.84,1032.2
BOOT2: C15.2 D3.1 U1.20 | length 193.4
  Top Layer w12.5: U1.20@1488.39,1032.2 1488.39,1078.39 1490.37,1080.37 1490.37,1117.93 C15.2@1502.44,1130 1502.44,1132.44 1530,1160 D3.1@1530,1208.35
COMP: C14.1 R10.2 U1.9 | length 250.4
  Top Layer w12.5: U1.9@1488.39,807.8 1488.39,750 1560,680 C14.1@1560,647.56
  Top Layer w25: C14.1@1560,647.56 R10.2@1620,647.56
CS_N: NT4.2 R15.2 | length 819.8
  Top Layer w15: R15.2@1807.56,1010 v1(1850,1010)
  Signal Layer 2 w10: NT4.2@1400,1560 1470,1560 1775,1255 1775,1105 1850,1030 v1(1850,1010)
CS_P: NT3.2 R13.2 | length 819.8
  Top Layer w15: R13.2@1807.56,1070 v1(1850,1070)
  Signal Layer 2 w10: NT3.2@1400,1620 1400,1590 1410,1580 1480,1580 1795,1265 1795,1125 v1(1850,1070)
CTL1: J5.2 R23.1 TP11.1 | length 1210.6
  Top Layer w25: TP11.1@1750,250 1870,370 R23.1@1870,477.44
  Signal Layer 2 w25: TP11.1@1750,250 1810,310 2410,310 2435,285 2435,165 2415,145 J5.2@2350,145
CTL2: J5.4 R20.1 TP10.1 | length 1190.7
  Top Layer w25: TP10.1@1550,250 1655,355 1765,355 1810,400 R20.1@1810,477.44
  Signal Layer 2 w25: TP10.1@1550,250 1712.5,87.5 2192.5,87.5 J5.4@2250,145
DITH: C9.2 U1.5 | length 305
  Top Layer w12.5: C9.2@1200,647.56 1200,680 1317.43,680 ; 1320,680 1386.02,746.02 U1.5@1386.02,807.8
EN: Q5.3 R1.1 R4.2 TP5.1 U1.1 | length 1172.9
  Top Layer w15: Q5.3@975,687.24 980,692.24 v1(980,800) R4.2@1027.44,800 ; v1(1235,800) 1260,800 1267.8,807.8 U1.1@1283.66,807.8
  Top Layer w25: R4.2@1027.44,800 R4.2@1030,802.56 R1.1@1030,857.44
  Bottom Layer w12.5: v1(980,800) v1(1235,800)
  Bottom Layer w25: TP5.1@750,250 980,480 v1(980,800)
EN_IN/PGOOD: J5.8 R9.1 TP7.1 U1.17 | length 2438.7
  Top Layer w12.5: U1.17@1565.16,1032.2 1565.16,1084.58 1590.95,1110.37 1602.81,1110.37 R9.1@1622.44,1130 1640,1147.56 1640,1160 v1(1650,1170)
  Top Layer w25: TP7.1@1150,250 1312.5,87.5 1992.5,87.5 J5.8@2050,145
  Bottom Layer w25: TP7.1@1150,250 1370,470 1610,470 1650,510 v1(1650,1170)
FB: R19.2 R21.1 R22.2 R24.2 U1.11 | length 524.1
  Top Layer w12.5: U1.11@1539.57,807.8 1539.57,769.25 1598.44,710.37 1724.63,710.37 1750,685 R24.2@1750,647.56
  Top Layer w25: R24.2@1750,647.56 R19.2@1810,647.56 R22.2@1870,647.56 1875.12,647.56 R21.1@1930,702.44
GND: C1.2 C2.2 C5.2 C6.2 C7.2 C8.1 C9.1 C10.2 C11.2 C12.1 C13.2 C14.2 C16.2 C19.2 C20.2 Cin1.2 Cin2.2 Cin3.2 Cin4.2 Co1.2 Co2.2 Co3.2 Co4.2 J3.1 J4.1 J5.1 J5.3 J5.5 J5.7 J5.9 J7.1 J7.3 J7.5 J7.7 NT4.1 Q5.2 R4.1 R11.1 R12.1 R24.1 RS2.1 TP3.1 TP4.1 TP13.1 U1.10 U1.22 U1.29 U2.2 U2.3 U2.6 U2.7 | length 811.1
  Top Layer w12.5: U1.29@1437.2,932.8 U1.22@1437.2,1032.2 1437.2,1129.65 C6.2@1437.56,1130 ; U1.29@1513.98,866.02 U1.10@1513.98,807.8 1513.98,766.02 1590,690 1670,690 1680,680 C13.2@1680,647.56 1682.56,645 1715,645 1715,595 1717.56,592.44 R24.1@1750,592.44
  Top Layer w20: RS2.1@1400,1473.86 v1(1400,1520) ; v1(1410,1210) 1435.39,1184.61 1435.39,1132.17 C6.2@1437.56,1130
  Signal Layer 2 w10: v1(1400,1520) NT4.1@1400,1540
  other v1: 1975,475 1200,550 1350,550 1710,550 1145,745 1371.26,880.63 1410.63,880.63 1450,880.63 1489.37,880.63 1528.74,880.63 1371.26,920 1410.63,920 1450,920 1489.37,920 1528.74,920 1371.26,959.37 1410.63,959.37 1450,959.37 1489.37,959.37 1528.74,959.37 1845,1190
  other v2: 500,350 775,625 1370,1410 1430,1410 500,2250 1050,2250 1750,2250 2350,2250
HDRV1_N: C4.2 L1.1 Q2.1 Q2.2 Q2.3 Q4.5 Q4.6 Q4.7 Q4.8 Q4.9 U1.28 | length 982.9
  Top Layer w12.5: Q2.3@1042.2,1810.53 1042.2,1857.2 v1(1045,1860)
  Top Layer w15: U1.28@1283.66,1032.2 1283.66,1056.34 1262.44,1077.56 C4.2@1262.44,1130 1250,1142.44 v1@1250,1291 ; v1@1250,1291 1248,1293 v1(1250,1295) v1@1250,1291
  Bottom Layer w12.5: v1(1045,1860) 1045,1816.03 1230,1631.03 1230,1340 1250,1320 v1(1250,1295)
HDRV1_P: RH1.1 U1.27 | length 223.1
  Top Layer w15: v1(1210,1160) RH1.1@1210,1202.44 ; v1(1300,1090) 1309.25,1080.75 U1.27@1309.25,1032.2
  Bottom Layer w15: v1(1210,1160) 1230,1160 v1(1300,1090)
HDRV2_N: C15.1 L1.2 Q1.1 Q1.2 Q1.3 Q3.5 Q3.6 Q3.7 Q3.8 Q3.9 U1.18 | length 1024
  Top Layer w12.5: U1.18@1539.57,1032.2 1541.25,1033.89 1541.25,1089.48 1557.56,1105.79 C15.1@1557.56,1130 1557.56,1167.56 1570,1180 v1(1570,1295) ; Q1.3@1712.2,1810.53 1712.2,1857.2 v1(1715,1860)
  Bottom Layer w12.5: v1(1570,1295) 1570,1315.35 1589.65,1335 1590,1535 1590,1541.03 1666.59,1617.62 1666.59,1843.41 1660,1850 1660,1870 1675,1885 1705,1885 1715,1875 v1(1715,1860)
HDRV2_P: RH2.2 U1.19 | length 212.9
  Top Layer w12.5: U1.19@1513.98,1032.2 v1@1513.98,1088.98 ; v1(1590,1165) 1595,1165 1610,1180 RH2.2@1610,1202.44
  Top Layer w15: v1@1513.98,1088.98 v1(1515,1090)
  Bottom Layer w12.5: v1(1515,1090) v1(1590,1165)
ISNS_OUT_N: NT2.1 R16.1 | length 870.6
  Top Layer w20: R16.1@1807.56,770 v1(1845,770)
  Signal Layer 2 w10: v1(1845,770) 1925,850 NT2.1@1925,1565
  Bottom Layer w10: v1(1845,770) v1@1850,770
ISNS_OUT_P: NT1.1 R17.1 | length 824.9
  Top Layer w20: R17.1@1807.56,830 v1(1845,830)
  Signal Layer 2 w10: v1(1845,830) 1845.86,829.14 1875.86,829.14 1905,858.28 1905,1545 NT1.1@1885,1565
LDRV1: RL1.1 U1.25 | length 174.6
  Top Layer w12.5: RL1.1@1350,1202.44 1350,1100 1360.43,1089.57 U1.25@1360.43,1032.2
